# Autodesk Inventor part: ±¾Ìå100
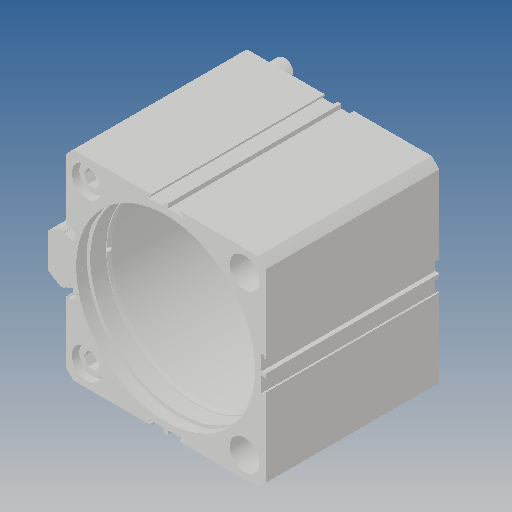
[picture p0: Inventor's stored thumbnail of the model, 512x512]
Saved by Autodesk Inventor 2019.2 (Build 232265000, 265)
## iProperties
Created: 2013-07
Part Number: ±¾Ìå100
Material: Ogólny
Document SubType Name: Modeling
Designer: CADENGINEERING4
Density: 1 g/cm^3
Appearance: Domyślna
Author: CADENGINEERING4
Revision Number: ÈÎºÎ
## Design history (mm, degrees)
feature "hexagon socket head cap screws gb_GB_FASTENER_SCREWS_HSHCS M"
feature "hexagon socket head cap screws gb_GB_FASTENER_SCREWS_HSHCS M"
feature "ÇÐ³ý-Ðý×ª1"
node "Bryła1"
node "Bryła2"
node "Bryła3"
